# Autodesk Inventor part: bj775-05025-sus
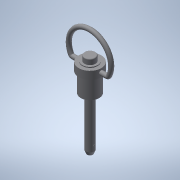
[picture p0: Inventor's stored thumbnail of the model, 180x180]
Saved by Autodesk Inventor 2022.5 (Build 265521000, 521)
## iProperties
Created: 2016-12
Part Number: bj775-05025-sus
Material: 一般
Document SubType Name: Modeling
Designer: imaocorp
Density: 1 g/cm^3
Appearance: 既定
Author: imaocorp
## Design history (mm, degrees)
node "bj775-05025-sus.x_t1"
node "bj775-05025-sus"
node "Base1"
